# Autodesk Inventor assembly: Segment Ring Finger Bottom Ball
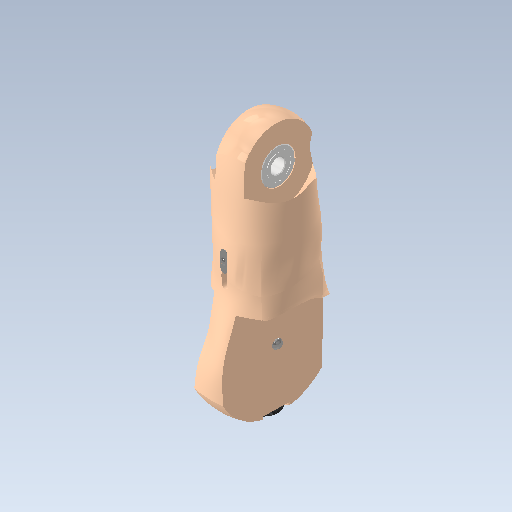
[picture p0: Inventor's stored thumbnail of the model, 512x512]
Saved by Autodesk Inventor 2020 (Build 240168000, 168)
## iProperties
Created: 2019-10
Part Number: Segment Ring Finger Bottom Ball
Document SubType Name: Assembly
Designer: yello
Author: yello
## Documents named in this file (8)
- D:\1-Cours-2021-22\1STI2D\ETLV\AI\Prototype 2 (Realistic Hand)\Segment Ring Finger Bottom Ball.iam
- D:\1-Cours-2021-22\1STI2D\ETLV\AI\Prototype 2 (Realistic Hand)\Segment Ring Finger Bottom.ipt
- D:\1-Cours-2021-22\1STI2D\ETLV\AI\Prototype 2 (Realistic Hand)\Lock.ipt
- D:\1-Cours-2021-22\1STI2D\ETLV\AI\Prototype 2 (Realistic Hand)\Push Part.ipt
- D:\1-Cours-2021-22\1STI2D\ETLV\AI\Prototype 2 (Realistic Hand)\Ball.ipt
- D:\1-Cours-2021-22\1STI2D\ETLV\AI\Prototype 2 (Realistic Hand)\Spring.ipt
- D:\1-Cours-2021-22\1STI2D\ETLV\AI\Prototype 2 (Realistic Hand)\Plug 2.ipt
- D:\1-Cours-2021-22\1STI2D\ETLV\AI\Prototype 2 (Realistic Hand)\Bearings.iam
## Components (8 placed, 7 different names)
1. Segment Ring Finger Bottom:1 — Mate:1, Mate:4, Mate:5, Mate:6, Mate:7, Mate:8, Mate:9, Mate:10, Flush:1
2. Lock:1 — Mate:2, Mate:3, Mate:4
3. Push Part:1 — Mate:1, Mate:2, Mate:3
4. Ball:1 — Mate:5
5. Ball:2 — Mate:6
6. Spring:1 — Mate:7
7. Plug 2:1 — Mate:8, Mate:9
8. Bearings:1 [sub-assembly] — Mate:10, Flush:1
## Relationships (11: Mate 10, Flush 1)
- Mate:1: Segment Ring Finger Bottom:1 ↔ Push Part:1
- Mate:2: Lock:1 ↔ Push Part:1
- Mate:3: Lock:1 ↔ Push Part:1
- Mate:4: Segment Ring Finger Bottom:1 ↔ Lock:1
- Mate:5: Segment Ring Finger Bottom:1 ↔ Ball:1
- Mate:6: Segment Ring Finger Bottom:1 ↔ Ball:2
- Mate:7: Segment Ring Finger Bottom:1 ↔ Spring:1
- Mate:8: Segment Ring Finger Bottom:1 ↔ Plug 2:1
- Mate:9: Segment Ring Finger Bottom:1 ↔ Plug 2:1
- Mate:10: Segment Ring Finger Bottom:1 ↔ Bearings:1
- Flush:1: Segment Ring Finger Bottom:1 ↔ Bearings:1
